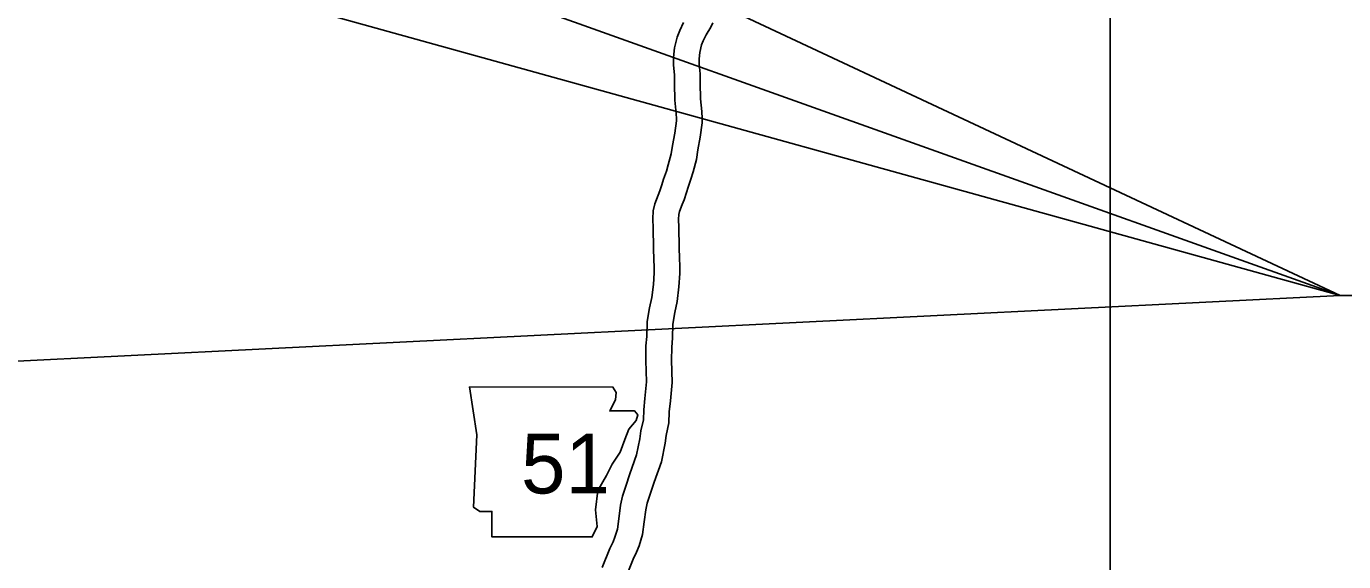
# Model space of a CAD drawing. Extents: x 1373862 to 1377080, y 1164775 to 1170415.
# Drawn here: x 1374487.3 to 1374641.2, y 1169967.7 to 1170030.2 of the extents above; entities that cross this region are included whole.
import ezdxf

# ---------------------------------------------------------------- set-up
doc = ezdxf.new("R2010")
doc.units = 0
doc.layers.add('1', color=7, linetype='Continuous')
doc.layers.add('Default', color=7, linetype='Continuous')

msp = doc.modelspace()

# ---------------------------------------------------------------- linework, layer by layer
at = {"layer": '1'}
for p, q in [((1374155.09, 1170226.04), (1374640.76, 1169998.76)), ((1374172.84, 1170165.77), (1374640.76, 1169998.76)), ((1374199.55, 1170121.07), (1374640.76, 1169998.76)), ((1374312.03, 1169982.46), (1374640.76, 1169998.76)), ((1374640.76, 1169998.76), (1374847.27, 1169998.76))]:
    msp.add_line(p, q, dxfattribs=at)
msp.add_lwpolyline([(1373884.49, 1170388.77), (1374613.88, 1170388.77), (1374613.88, 1169861.94), (1373884.49, 1169861.94)], close=True, dxfattribs=at)
at = {"layer": 'Default'}
for points in [[(1374564.08, 1170030.6), (1374563.64, 1170029.7), (1374563.33, 1170028.92), (1374563.02, 1170027.67), (1374562.89, 1170026.54), (1374562.91, 1170025.66), (1374563, 1170024.45), (1374563.03, 1170023.45), (1374563.07, 1170021.55), (1374563.21, 1170019.99), (1374563.25, 1170019.36), (1374563.25, 1170019.14), (1374563.05, 1170017.69), (1374562.79, 1170016.25), (1374562.64, 1170015.28), (1374562.29, 1170014.01), (1374562.07, 1170013.25), (1374561.75, 1170012.33), (1374561.55, 1170011.67), (1374561.31, 1170010.95), (1374561.11, 1170010.46), (1374560.72, 1170009.44), (1374560.54, 1170008.64), (1374560.47, 1170007.71), (1374560.53, 1170006.6), (1374560.55, 1170004.3), (1374560.61, 1170002.89), (1374560.65, 1170002.15), (1374560.66, 1170001.41), (1374560.55, 1170000.05), (1374560.36, 1169998.53), (1374560.11, 1169997.32), (1374559.84, 1169995.7), (1374559.8, 1169993.98), (1374559.69, 1169992.86), (1374559.67, 1169991.17), (1374559.73, 1169988.68), (1374559.57, 1169986.75), (1374559.42, 1169985.4), (1374559.38, 1169984.26), (1374559.1, 1169982.94), (1374558.97, 1169982.03), (1374558.6, 1169980.14), (1374557.82, 1169977.95), (1374557.33, 1169976.49), (1374556.96, 1169975.35), (1374556.7, 1169974.29), (1374556.5, 1169972.69), (1374556.35, 1169971.48), (1374556.07, 1169970.54), (1374555.85, 1169970.01), (1374555.47, 1169969.23), (1374554.56, 1169967.02)], [(1374567.48, 1170030.59), (1374567.25, 1170030.08), (1374566.72, 1170029.18), (1374566.38, 1170028.48), (1374566.19, 1170028.01), (1374565.98, 1170027.13), (1374565.89, 1170026.39), (1374565.91, 1170025.81), (1374566, 1170024.61), (1374566.03, 1170023.52), (1374566.07, 1170021.72), (1374566.21, 1170020.22), (1374566.26, 1170019.41), (1374566.24, 1170018.89), (1374566.02, 1170017.23), (1374565.75, 1170015.75), (1374565.57, 1170014.64), (1374565.18, 1170013.2), (1374564.93, 1170012.34), (1374564.61, 1170011.41), (1374564.41, 1170010.76), (1374564.13, 1170009.9), (1374563.9, 1170009.36), (1374563.6, 1170008.57), (1374563.52, 1170008.2), (1374563.48, 1170007.67), (1374563.53, 1170006.69), (1374563.55, 1170004.38), (1374563.61, 1170003.02), (1374563.64, 1170002.25), (1374563.66, 1170001.32), (1374563.53, 1169999.75), (1374563.33, 1169998.04), (1374563.05, 1169996.77), (1374562.84, 1169995.42), (1374562.79, 1169993.8), (1374562.69, 1169992.69), (1374562.67, 1169991.19), (1374562.73, 1169988.59), (1374562.55, 1169986.46), (1374562.41, 1169985.18), (1374562.37, 1169983.9), (1374562.06, 1169982.42), (1374561.93, 1169981.53), (1374561.5, 1169979.34), (1374560.66, 1169976.97), (1374560.18, 1169975.55), (1374559.84, 1169974.53), (1374559.66, 1169973.75), (1374559.48, 1169972.33), (1374559.3, 1169970.87), (1374558.91, 1169969.55), (1374558.59, 1169968.78), (1374558.21, 1169967.99), (1374557.4, 1169966.04)]]:
    msp.add_lwpolyline(points, dxfattribs=at)
msp.add_lwpolyline([(1374539.09, 1169988.08), (1374539.92, 1169982.49), (1374539.55, 1169974.03), (1374540.3, 1169973.56), (1374541.69, 1169973.56), (1374541.69, 1169970.58), (1374553.42, 1169970.58), (1374553.97, 1169971.79), (1374553.79, 1169973.75), (1374554.07, 1169975.98), (1374555.09, 1169977.75), (1374555.74, 1169979.05), (1374556.67, 1169980.45), (1374557.23, 1169981.93), (1374557.7, 1169983.14), (1374558.53, 1169984.17), (1374558.72, 1169984.82), (1374558.35, 1169985.28), (1374555.46, 1169985.28), (1374556.11, 1169986.59), (1374556.21, 1169987.42), (1374555.82, 1169988.07)], close=True, dxfattribs=at)

# ---------------------------------------------------------------- texts
msp.add_text('51', height=6.97, dxfattribs=at).set_placement((1374545.1, 1169975.65))

doc.saveas('drawing.dxf')
